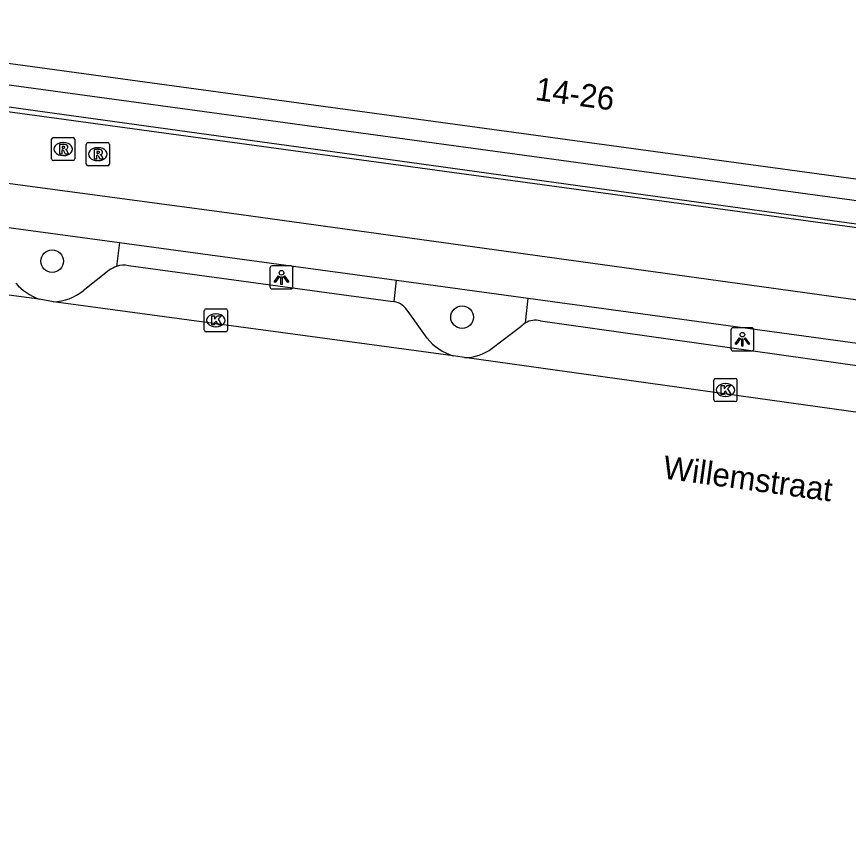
# Model space of a CAD drawing. Extents: x 160676 to 161153, y 383244 to 383713.
# Drawn here: x 160812.07 to 160848.04, y 383255.03 to 383290.54 of the extents above; entities that cross this region are included whole.
import ezdxf

# ---------------------------------------------------------------- set-up
doc = ezdxf.new("R2010")
doc.units = 0
for name, color, linetype in [('IMGEO_Berm_open', 7, 'Continuous'), ('IMGEO_Boom', 7, 'Continuous'), ('IMGEO_Fietspad_gesloten', 7, 'Continuous'), ('IMGEO_Kolk', 7, 'Continuous'), ('IMGEO_Lichtpunt', 7, 'Continuous'), ('IMGEO_Lijnafwatering', 7, 'Continuous'), ('IMGEO_Openbare_ruimte_label', 7, 'Continuous'), ('IMGEO_Pand', 7, 'Continuous'), ('IMGEO_Pand_nummerreeks', 7, 'Continuous'), ('IMGEO_Parkeervlak_open', 7, 'Continuous'), ('IMGEO_Rijbaan_lokaal_gesloten', 7, 'Continuous'), ('IMGEO_Rioolput', 7, 'Continuous'), ('IMGEO_Voetpad_open', 7, 'Continuous')]:
    doc.layers.add(name, color=color, linetype=linetype)

msp = doc.modelspace()

# ---------------------------------------------------------------- linework, layer by layer
at = {"layer": 'IMGEO_Berm_open'}
for points in [[(160816.508, 383280.767), (160816.39, 383279.735)], [(160828.392, 383278.214), (160828.488, 383279.134)], [(160834.067, 383277.286), (160834.185, 383278.357)]]:
    msp.add_lwpolyline(points, dxfattribs=at)
at = {"layer": 'IMGEO_Boom'}
for centre in [(160813.6, 383279.958), (160831.33, 383277.536)]:
    msp.add_circle(centre, 0.489, dxfattribs=at)
at = {"layer": 'IMGEO_Fietspad_gesloten'}
for points in [[(160794.456, 383285.635), (160802.2, 383284.6), (160821.26, 383282.051), (160905.957, 383270.323), (160917.876, 383268.672), (161015.584, 383255.032)], [(160810.848, 383281.538), (160816.508, 383280.767)], [(160816.508, 383280.767), (160828.488, 383279.134)], [(160828.488, 383279.134), (160834.185, 383278.357)], [(160834.185, 383278.357), (160852.13, 383275.911)]]:
    msp.add_lwpolyline(points, dxfattribs=at)
at = {"layer": 'IMGEO_Kolk'}
for p, q in [((160820.183, 383276.976), (160820.183, 383277.828)), ((160820.258, 383277.902), (160821.11, 383277.902)), ((160820.671, 383277.682), (160820.696, 383277.682)), ((160821.184, 383277.828), (160821.184, 383276.976)), ((160820.694, 383277.122), (160820.669, 383277.122)), ((160821.11, 383276.902), (160820.258, 383276.902)), ((160842.22, 383273.96), (160842.22, 383274.812)), ((160842.295, 383274.886), (160843.147, 383274.886)), ((160843.221, 383274.812), (160843.221, 383273.96)), ((160842.708, 383274.666), (160842.733, 383274.666)), ((160842.731, 383274.106), (160842.706, 383274.106)), ((160843.147, 383273.886), (160842.295, 383273.886))]:
    msp.add_line(p, q, dxfattribs=at)
for points in [[(160820.183, 383276.976), (160820.183, 383277.828)], [(160820.258, 383277.902), (160821.11, 383277.902)], [(160821.184, 383277.828), (160821.184, 383276.976)], [(160820.504, 383277.602), (160820.627, 383277.602), (160820.627, 383277.451), (160820.757, 383277.602), (160820.921, 383277.602), (160820.775, 383277.451), (160820.928, 383277.202), (160820.776, 383277.202), (160820.691, 383277.366), (160820.627, 383277.299), (160820.627, 383277.202), (160820.504, 383277.202), (160820.504, 383277.602)], [(160821.11, 383276.902), (160820.258, 383276.902)], [(160842.22, 383273.96), (160842.22, 383274.812)], [(160842.295, 383274.886), (160843.147, 383274.886)], [(160843.221, 383274.812), (160843.221, 383273.96)], [(160842.541, 383274.586), (160842.664, 383274.586), (160842.664, 383274.435), (160842.794, 383274.586), (160842.958, 383274.586), (160842.812, 383274.435), (160842.965, 383274.186), (160842.813, 383274.186), (160842.728, 383274.35), (160842.664, 383274.283), (160842.664, 383274.186), (160842.541, 383274.186), (160842.541, 383274.586)], [(160843.147, 383273.886), (160842.295, 383273.886)]]:
    msp.add_lwpolyline(points, dxfattribs=at)
for centre, start, end in [((160820.26, 383277.826), 91.552, 178.448), ((160820.26, 383277.826), 91.552, 178.448), ((160821.108, 383277.826), 1.552, 88.448), ((160821.108, 383277.826), 1.552, 88.448), ((160820.26, 383276.978), 181.552, 268.448), ((160820.26, 383276.978), 181.552, 268.448), ((160821.108, 383276.978), 271.552, 358.448), ((160821.108, 383276.978), 271.552, 358.448), ((160842.297, 383274.81), 91.552, 178.448), ((160842.297, 383274.81), 91.552, 178.448), ((160843.145, 383274.81), 1.552, 88.448), ((160843.145, 383274.81), 1.552, 88.448), ((160842.297, 383273.962), 181.552, 268.448), ((160842.297, 383273.962), 181.552, 268.448), ((160843.145, 383273.962), 271.552, 358.448), ((160843.145, 383273.962), 271.552, 358.448)]:
    msp.add_arc(centre, 0.0765, start, end, dxfattribs=at)
for centre, major_axis, ratio, start_param, end_param in [((160820.67, 383277.402), (-0.387, 0.002), 0.722429, 4.712389, 7.853982), ((160820.695, 383277.402), (-0.39, 0.002), 0.717154, 1.570796, 4.712389), ((160842.707, 383274.386), (-0.387, 0.002), 0.722429, 4.712389, 7.853982), ((160842.732, 383274.386), (-0.39, 0.002), 0.717154, 1.570796, 4.712389)]:
    msp.add_ellipse(centre, major_axis=major_axis, ratio=ratio, start_param=start_param, end_param=end_param, dxfattribs=at)
at = {"layer": 'IMGEO_Lichtpunt'}
for p, q in [((160823.022, 383279.66), (160823.022, 383278.853)), ((160823.022, 383279.66), (160823.022, 383278.853)), ((160823.924, 383279.755), (160823.116, 383279.755)), ((160823.924, 383279.755), (160823.116, 383279.755)), ((160824.018, 383278.853), (160824.018, 383279.66)), ((160824.018, 383278.853), (160824.018, 383279.66)), ((160823.116, 383278.759), (160823.924, 383278.759)), ((160823.116, 383278.759), (160823.924, 383278.759)), ((160842.955, 383276.982), (160842.955, 383276.175)), ((160842.955, 383276.982), (160842.955, 383276.175)), ((160843.857, 383277.077), (160843.049, 383277.077)), ((160843.857, 383277.077), (160843.049, 383277.077)), ((160843.951, 383276.175), (160843.951, 383276.982)), ((160843.951, 383276.175), (160843.951, 383276.982)), ((160843.049, 383276.081), (160843.857, 383276.081)), ((160843.049, 383276.081), (160843.857, 383276.081))]:
    msp.add_line(p, q, dxfattribs=at)
for points in [[(160823.396, 383279.324), (160823.435, 383279.296), (160823.247, 383279.034), (160823.209, 383279.061), (160823.396, 383279.324)], [(160823.498, 383279.276), (160823.545, 383279.276), (160823.545, 383278.954), (160823.498, 383278.954), (160823.498, 383279.276)], [(160823.608, 383279.296), (160823.646, 383279.323), (160823.833, 383279.061), (160823.794, 383279.033), (160823.608, 383279.296)], [(160843.329, 383276.646), (160843.368, 383276.618), (160843.18, 383276.356), (160843.142, 383276.383), (160843.329, 383276.646)], [(160843.431, 383276.598), (160843.478, 383276.598), (160843.478, 383276.276), (160843.431, 383276.276), (160843.431, 383276.598)], [(160843.541, 383276.618), (160843.579, 383276.645), (160843.766, 383276.383), (160843.727, 383276.355), (160843.541, 383276.618)]]:
    msp.add_lwpolyline(points, dxfattribs=at)
for centre in [(160823.521, 383279.458), (160843.454, 383276.78)]:
    msp.add_circle(centre, 0.0994, dxfattribs=at)
for centre, start, end in [((160823.116, 383279.66), 90, 180), ((160823.116, 383279.66), 90, 180), ((160823.924, 383279.66), 0, 90), ((160823.924, 383279.66), 0, 90), ((160823.116, 383278.853), 180, 270), ((160823.116, 383278.853), 180, 270), ((160823.924, 383278.853), 270, 0), ((160823.924, 383278.853), 270, 360), ((160843.049, 383276.982), 90, 180), ((160843.049, 383276.982), 90, 180), ((160843.857, 383276.982), 0, 90), ((160843.857, 383276.982), 0, 90), ((160843.049, 383276.175), 180, 270), ((160843.049, 383276.175), 180, 270), ((160843.857, 383276.175), 270, 0), ((160843.857, 383276.175), 270, 360)]:
    msp.add_arc(centre, 0.0946, start, end, dxfattribs=at)
at = {"layer": 'IMGEO_Lijnafwatering'}
for points in [[(160825.728, 383284.689), (160819.957, 383285.485), (160802.645, 383287.876)], [(160848.81, 383281.501), (160837.269, 383283.095), (160825.728, 383284.689)]]:
    msp.add_lwpolyline(points, dxfattribs=at)
at = {"layer": 'IMGEO_Pand'}
msp.add_lwpolyline([(160796.9, 383290.54), (160810.196, 383288.729), (160850.265, 383283.27), (160863.734, 383281.435), (160876.566, 383279.687)], dxfattribs=at)
at = {"layer": 'IMGEO_Parkeervlak_open'}
for points in [[(160816.068, 383279.564), (160814.939, 383278.675)], [(160816.898, 383279.766), (160828.237, 383278.23), (160828.392, 383278.214)], [(160829.819, 383276.632), (160828.998, 383277.777)], [(160834.72, 383277.375), (160851.999, 383274.936)], [(160832.635, 383276.197), (160833.888, 383277.144)]]:
    msp.add_lwpolyline(points, dxfattribs=at)
for centre, radius, start, end in [((160816.696, 383278.771), 1.012, 107.5905, 128.3511), ((160816.705, 383278.753), 1.031, 79.202, 107.7821), ((160813.858, 383280.597), 2.421, 221.0527, 250.1293), ((160813.548, 383280.455), 2.259, 272.8332, 307.9939), ((160828.223, 383277.341), 0.889, 29.3593, 79.0483), ((160834.498, 383276.565), 0.84, 74.6568, 120.8657), ((160834.516, 383276.536), 0.874, 120.9154, 135.9343), ((160831.571, 383278.014), 2.232, 218.2804, 253.8499), ((160831.444, 383277.732), 1.943, 269.6857, 307.8122)]:
    msp.add_arc(centre, radius, start, end, dxfattribs=at)
at = {"layer": 'IMGEO_Rijbaan_lokaal_gesloten'}
for points in [[(160813.035, 383278.32), (160800.901, 383279.923)], [(160813.66, 383278.199), (160813.035, 383278.32)], [(160830.95, 383275.871), (160813.66, 383278.199)], [(160831.433, 383275.789), (160830.95, 383275.871)], [(160854.652, 383272.548), (160831.433, 383275.789)]]:
    msp.add_lwpolyline(points, dxfattribs=at)
at = {"layer": 'IMGEO_Rioolput'}
for p, q in [((160813.58, 383284.383), (160813.58, 383285.235)), ((160813.655, 383285.309), (160814.507, 383285.309)), ((160814.581, 383285.235), (160814.581, 383284.383)), ((160814.068, 383285.089), (160814.093, 383285.089)), ((160815.079, 383284.163), (160815.079, 383285.015)), ((160815.154, 383285.089), (160816.006, 383285.089)), ((160815.567, 383284.869), (160815.592, 383284.869)), ((160816.08, 383285.015), (160816.08, 383284.163)), ((160814.091, 383284.529), (160814.066, 383284.529)), ((160814.507, 383284.309), (160813.655, 383284.309)), ((160815.59, 383284.309), (160815.565, 383284.309)), ((160816.006, 383284.089), (160815.154, 383284.089))]:
    msp.add_line(p, q, dxfattribs=at)
for points in [[(160813.58, 383284.383), (160813.58, 383285.235)], [(160813.655, 383285.309), (160814.507, 383285.309)], [(160814.581, 383285.235), (160814.581, 383284.383)], [(160814.169, 383285.007), (160813.917, 383285.009), (160813.917, 383284.609)], [(160814.095, 383284.928), (160814.041, 383284.928), (160814.041, 383284.847)], [(160815.079, 383284.163), (160815.079, 383285.015)], [(160815.154, 383285.089), (160816.006, 383285.089)], [(160816.08, 383285.015), (160816.08, 383284.163)], [(160813.917, 383284.609), (160814.041, 383284.609), (160814.041, 383284.771), (160814.052, 383284.771)], [(160814.041, 383284.847), (160814.093, 383284.847)], [(160814.099, 383284.742), (160814.17, 383284.609), (160814.31, 383284.609), (160814.245, 383284.735)], [(160815.668, 383284.787), (160815.416, 383284.789), (160815.416, 383284.389)], [(160815.416, 383284.389), (160815.54, 383284.389), (160815.54, 383284.551), (160815.551, 383284.551)], [(160815.594, 383284.708), (160815.54, 383284.708), (160815.54, 383284.627)], [(160815.54, 383284.627), (160815.592, 383284.627)], [(160815.598, 383284.522), (160815.669, 383284.389), (160815.809, 383284.389), (160815.744, 383284.515)], [(160814.507, 383284.309), (160813.655, 383284.309)], [(160816.006, 383284.089), (160815.154, 383284.089)]]:
    msp.add_lwpolyline(points, dxfattribs=at)
for centre, radius, start, end in [((160813.657, 383285.233), 0.0765, 91.552, 178.448), ((160813.657, 383285.233), 0.0765, 91.552, 178.448), ((160814.505, 383285.233), 0.0765, 1.552, 88.448), ((160814.505, 383285.233), 0.0765, 1.552, 88.448), ((160814.101, 383284.832), 0.0964, 77.0061, 93.1865), ((160814.115, 383284.889), 0.0378, 276.6634, 79.6772), ((160814.168, 383284.897), 0.109, 350.3612, 89.416), ((160814.166, 383284.897), 0.112, 277.5842, 350.9817), ((160815.156, 383285.013), 0.0765, 91.552, 178.448), ((160815.156, 383285.013), 0.0765, 91.552, 178.448), ((160816.004, 383285.013), 0.0765, 1.552, 88.448), ((160816.004, 383285.013), 0.0765, 1.552, 88.448), ((160814.051, 383284.718), 0.0533, 26.0293, 88.6989), ((160814.077, 383285.036), 0.19, 274.7715, 282.9687), ((160814.15, 383284.682), 0.108, 29.5134, 73.7905), ((160815.55, 383284.498), 0.0533, 26.0293, 88.6989), ((160815.576, 383284.816), 0.19, 274.7715, 282.9687), ((160815.6, 383284.612), 0.0964, 77.0061, 93.1865), ((160815.614, 383284.669), 0.0378, 276.6634, 79.6772), ((160815.667, 383284.677), 0.109, 350.3612, 89.416), ((160815.665, 383284.677), 0.112, 277.5842, 350.9817), ((160815.649, 383284.462), 0.108, 29.5134, 73.7905), ((160813.657, 383284.385), 0.0765, 181.552, 268.448), ((160813.657, 383284.385), 0.0765, 181.552, 268.448), ((160814.505, 383284.385), 0.0765, 271.552, 358.448), ((160814.505, 383284.385), 0.0765, 271.552, 358.448), ((160815.156, 383284.165), 0.0765, 181.552, 268.448), ((160815.156, 383284.165), 0.0765, 181.552, 268.448), ((160816.004, 383284.165), 0.0765, 271.552, 358.448), ((160816.004, 383284.165), 0.0765, 271.552, 358.448)]:
    msp.add_arc(centre, radius, start, end, dxfattribs=at)
for centre, major_axis, ratio, start_param, end_param in [((160814.067, 383284.809), (-0.387, 0.002), 0.722429, 4.712389, 7.853982), ((160814.092, 383284.809), (-0.39, 0.002), 0.717154, 1.570796, 4.712389), ((160815.566, 383284.589), (-0.387, 0.002), 0.722429, 4.712389, 7.853982), ((160815.591, 383284.589), (-0.39, 0.002), 0.717154, 1.570796, 4.712389)]:
    msp.add_ellipse(centre, major_axis=major_axis, ratio=ratio, start_param=start_param, end_param=end_param, dxfattribs=at)
at = {"layer": 'IMGEO_Voetpad_open'}
for points in [[(160796.9, 383290.54), (160796.624, 383289.648), (160876.281, 383278.779), (160876.566, 383279.687)], [(160856.427, 383280.313), (160809.546, 383286.711)]]:
    msp.add_lwpolyline(points, dxfattribs=at)

# ---------------------------------------------------------------- texts
at = {"layer": 'IMGEO_Openbare_ruimte_label'}
msp.add_text('Willemstraat', height=1, rotation=352.1858, dxfattribs=at).set_placement((160839.979, 383270.565))
at = {"layer": 'IMGEO_Pand_nummerreeks'}
msp.add_text('14-26', height=1, rotation=352.2422, dxfattribs=at).set_placement((160834.455, 383286.938))

doc.saveas('drawing.dxf')
